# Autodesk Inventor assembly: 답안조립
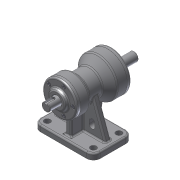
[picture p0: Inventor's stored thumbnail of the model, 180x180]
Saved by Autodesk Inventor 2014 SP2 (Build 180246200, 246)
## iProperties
Created: 2012-11
Part Number: 답안조립
Document SubType Name: Assembly
Designer: 손기택
Author: 손기택
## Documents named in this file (8)
- C:\Users\201-15\Documents\Inventor\450805V1040\답안조립.iam
- C:\Users\201-15\Documents\Inventor\450805V1040\본체.ipt
- C:\Users\201-15\Documents\Inventor\450805V1040\앞커버.ipt
- C:\Users\201-15\Documents\Inventor\450805V1040\뒤커버.ipt
- C:\Users\201-15\Documents\Inventor\450805V1040\베어링 6203.ipt
- C:\Users\201-15\Documents\Inventor\450805V1040\베어링 6205.ipt
- C:\Users\201-15\Documents\Inventor\450805V1040\축.ipt
- C:\Users\201-15\Documents\Inventor\450805V1040\M4x0.5.ipt
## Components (10 placed, 1 different names)
1. M4x0.5:1
2. M4x0.5:3
3. M4x0.5:4
4. M4x0.5:5
5. M4x0.5:6
6. M4x0.5:7
7. M4x0.5:8
8. M4x0.5:9
9. M4x0.5:10
10. M4x0.5:11
